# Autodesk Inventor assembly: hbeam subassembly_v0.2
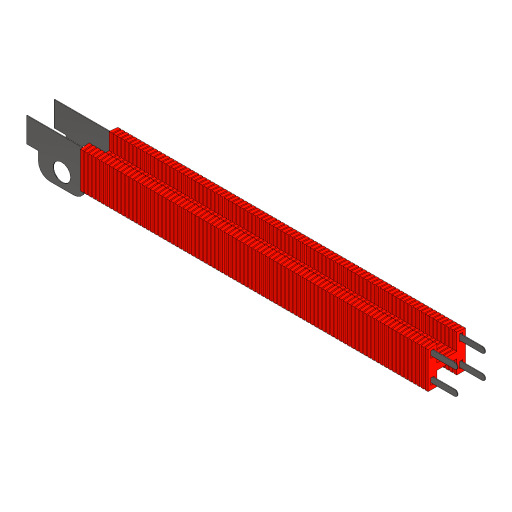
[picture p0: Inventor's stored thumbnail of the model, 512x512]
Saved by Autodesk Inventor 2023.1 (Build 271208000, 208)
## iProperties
Created: 2023-03
Part Number: hbeam subassembly_v0.2
Document SubType Name: Assembly
Designer: Fabian
Author: Fabian
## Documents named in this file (3)
- C:\Users\Fabian\OneDrive\Delft\CPMM\Machined_Prototype\Mods\Assemblies\hbeam subassembly_v0.2.iam
- C:\Users\Fabian\OneDrive\Delft\CPMM\Machined_Prototype\Mods\Parts\multiPartFlatSpringThin.ipt
- C:\Users\Fabian\OneDrive\Delft\CPMM\Machined_Prototype\Mods\Parts\multipartHbeamv0.2.ipt
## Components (87 placed, 2 different names)
1. multiPartFlatSpringThin:1
2. multiPartFlatSpringThin:2 — Mate:1, Mate:2, Mate:3
3. multipartHbeamv0.2:1 — Mate:1, Mate:2, Mate:3
4. multipartHbeamv0.2:2
5. multipartHbeamv0.2:3
6. multipartHbeamv0.2:4
7. multipartHbeamv0.2:5
8. multipartHbeamv0.2:6
9. multipartHbeamv0.2:7
10. multipartHbeamv0.2:8
11. multipartHbeamv0.2:9
12. multipartHbeamv0.2:10
13. multipartHbeamv0.2:11
14. multipartHbeamv0.2:12
15. multipartHbeamv0.2:13
16. multipartHbeamv0.2:14
17. multipartHbeamv0.2:15
18. multipartHbeamv0.2:16
19. multipartHbeamv0.2:17
20. multipartHbeamv0.2:18
21. multipartHbeamv0.2:19
22. multipartHbeamv0.2:20
23. multipartHbeamv0.2:21
24. multipartHbeamv0.2:22
25. multipartHbeamv0.2:23
26. multipartHbeamv0.2:24
27. multipartHbeamv0.2:25
28. multipartHbeamv0.2:26
29. multipartHbeamv0.2:27
30. multipartHbeamv0.2:28
31. multipartHbeamv0.2:29
32. multipartHbeamv0.2:30
33. multipartHbeamv0.2:31
34. multipartHbeamv0.2:32
35. multipartHbeamv0.2:33
36. multipartHbeamv0.2:34
37. multipartHbeamv0.2:35
38. multipartHbeamv0.2:36
39. multipartHbeamv0.2:37
40. multipartHbeamv0.2:38
41. multipartHbeamv0.2:39
42. multipartHbeamv0.2:40
43. multipartHbeamv0.2:41
44. multipartHbeamv0.2:42
45. multipartHbeamv0.2:43
46. multipartHbeamv0.2:44
47. multipartHbeamv0.2:45
48. multipartHbeamv0.2:46
49. multipartHbeamv0.2:47
50. multipartHbeamv0.2:48
51. multipartHbeamv0.2:49
52. multipartHbeamv0.2:50
53. multipartHbeamv0.2:51
54. multipartHbeamv0.2:52
55. multipartHbeamv0.2:53
56. multipartHbeamv0.2:54
57. multipartHbeamv0.2:55
58. multipartHbeamv0.2:56
59. multipartHbeamv0.2:57
60. multipartHbeamv0.2:58
61. multipartHbeamv0.2:59
62. multipartHbeamv0.2:60
63. multipartHbeamv0.2:61
64. multipartHbeamv0.2:62
65. multipartHbeamv0.2:63
66. multipartHbeamv0.2:64
67. multipartHbeamv0.2:65
68. multipartHbeamv0.2:66
69. multipartHbeamv0.2:67
70. multipartHbeamv0.2:68
71. multipartHbeamv0.2:69
72. multipartHbeamv0.2:70
73. multipartHbeamv0.2:71
74. multipartHbeamv0.2:72
75. multipartHbeamv0.2:73
76. multipartHbeamv0.2:74
77. multipartHbeamv0.2:75
78. multipartHbeamv0.2:76
79. multipartHbeamv0.2:77
80. multipartHbeamv0.2:78
81. multipartHbeamv0.2:79
82. multipartHbeamv0.2:80
83. multipartHbeamv0.2:81
84. multipartHbeamv0.2:82
85. multipartHbeamv0.2:83
86. multipartHbeamv0.2:84
87. multipartHbeamv0.2:85
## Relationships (3: Mate 3)
- Mate:1: multiPartFlatSpringThin:2 ↔ multipartHbeamv0.2:1
- Mate:2: multiPartFlatSpringThin:2 ↔ multipartHbeamv0.2:1
- Mate:3: multiPartFlatSpringThin:2 ↔ multipartHbeamv0.2:1
